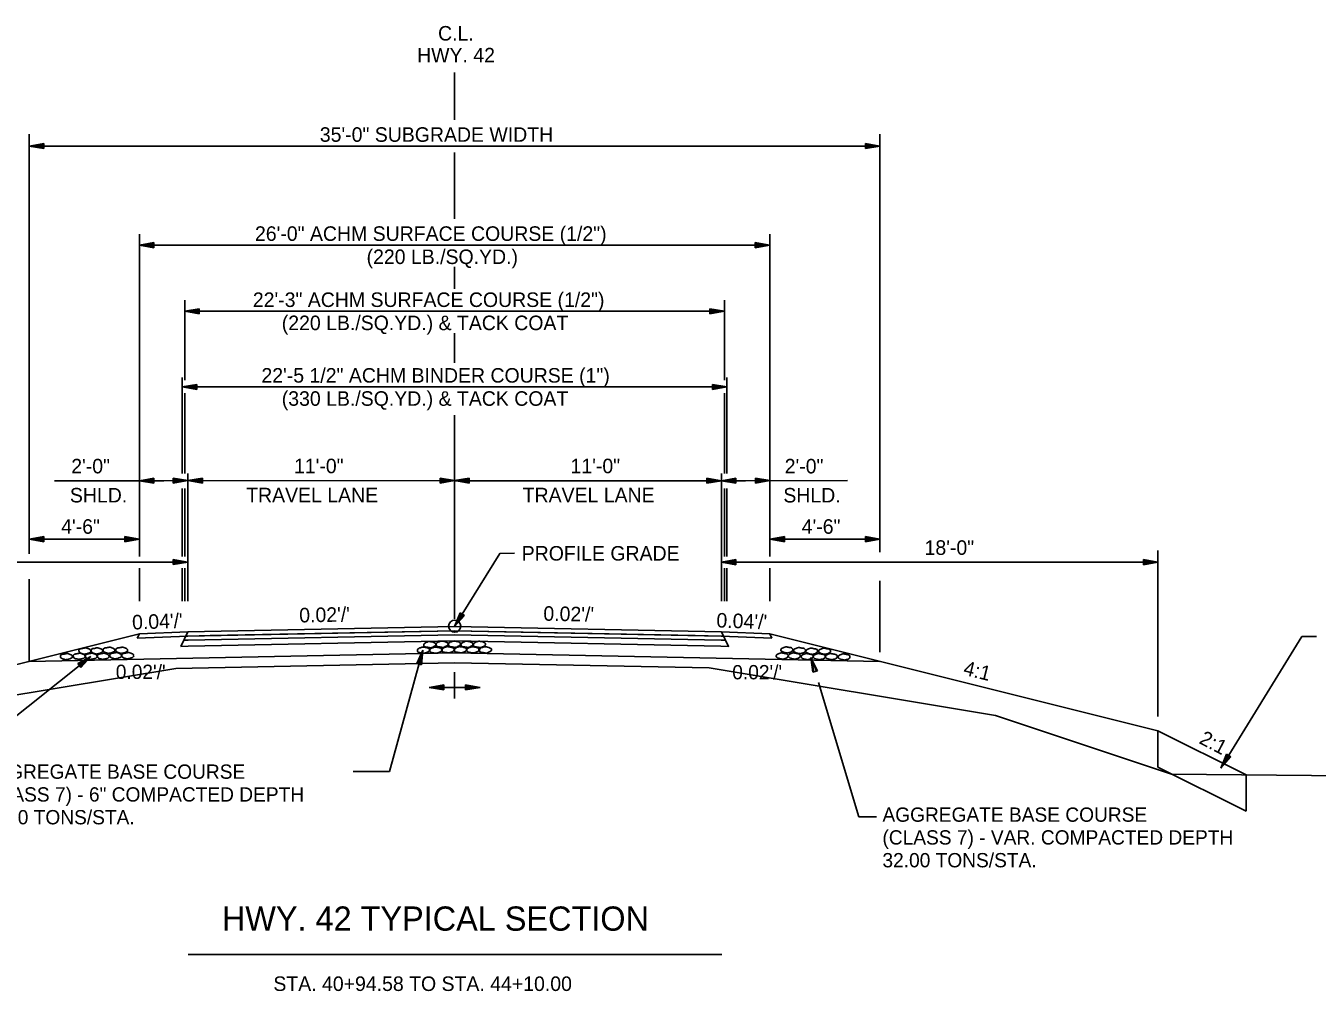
# Model space of a CAD drawing. Extents: x 1461570 to 1461697, y 1686711 to 1686957.
# Drawn here: x 1461599.6 to 1461652.8, y 1686903.7 to 1686943.6 of the extents above; entities that cross this region are included whole.
import ezdxf

# ---------------------------------------------------------------- set-up
doc = ezdxf.new("R2010")
doc.units = 0
for name, color, linetype in [('1', 7, 'Continuous'), ('19', 7, 'Continuous'), ('20', 7, 'Continuous'), ('3', 7, 'Continuous'), ('42', 7, 'Continuous'), ('Default', 7, 'Continuous'), ('Level 1', 7, 'Continuous'), ('Level 9', 7, 'Continuous'), ('R_Draft', 7, 'Continuous'), ('R_Prop Surface', 7, 'Continuous'), ('R_RIP_RAP', 7, 'Continuous')]:
    doc.layers.add(name, color=color, linetype=linetype)

# ---------------------------------------------------------------- blocks, each defined once
blk = doc.blocks.new('ROCKS')
at = {"layer": '1'}
blk.add_spline([(0.013, 0.06), (0.053, 0.053), (0.107, 0.033), (0.133, 0.013), (0.133, -0.007), (0.12, -0.033), (0.107, -0.04), (0.073, -0.053), (0.033, -0.067), (0.013, -0.067), (-0.02, -0.06), (-0.06, -0.053), (-0.087, -0.047), (-0.113, -0.02), (-0.113, -0.007), (-0.107, 0.02), (-0.087, 0.033), (-0.067, 0.047), (-0.033, 0.053), (-0.02, 0.06), (0.013, 0.06)], degree=3, dxfattribs=at)

msp = doc.modelspace()

# ---------------------------------------------------------------- linework, layer by layer
at = {"layer": '19'}
for p, q in [((1461599.708, 1686922.374), (1461600.308, 1686922.479)), ((1461600.308, 1686922.269), (1461599.708, 1686922.374)), ((1461599.868, 1686922.389), (1461600.308, 1686922.424)), ((1461600.308, 1686922.319), (1461599.868, 1686922.359)), ((1461600.308, 1686922.479), (1461600.308, 1686922.269)), ((1461603.646, 1686922.269), (1461603.646, 1686922.479)), ((1461603.646, 1686922.479), (1461604.246, 1686922.374)), ((1461603.646, 1686922.424), (1461604.086, 1686922.389)), ((1461604.246, 1686922.374), (1461603.646, 1686922.269)), ((1461604.086, 1686922.359), (1461603.646, 1686922.319)), ((1461630.245, 1686922.374), (1461630.845, 1686922.479)), ((1461630.845, 1686922.269), (1461630.245, 1686922.374)), ((1461630.405, 1686922.389), (1461630.845, 1686922.424)), ((1461630.845, 1686922.319), (1461630.405, 1686922.359)), ((1461630.845, 1686922.479), (1461630.845, 1686922.269)), ((1461634.183, 1686922.269), (1461634.183, 1686922.479)), ((1461634.183, 1686922.479), (1461634.783, 1686922.374)), ((1461634.183, 1686922.424), (1461634.623, 1686922.389)), ((1461634.783, 1686922.374), (1461634.183, 1686922.269)), ((1461634.623, 1686922.359), (1461634.183, 1686922.319)), ((1461617.246, 1686918.764), (1461617.469, 1686919.33)), ((1461617.647, 1686919.221), (1461617.246, 1686918.764)), ((1461617.319, 1686918.904), (1461617.512, 1686919.298)), ((1461617.606, 1686919.242), (1461617.342, 1686918.893)), ((1461617.469, 1686919.33), (1461617.647, 1686919.221)), ((1461604.246, 1686918.464), (1461604.161, 1686918.293)), ((1461604.246, 1686918.464), (1461604.161, 1686918.293)), ((1461606.246, 1686918.544), (1461604.246, 1686918.464)), ((1461606.246, 1686918.544), (1461605.951, 1686917.948)), ((1461606.161, 1686918.373), (1461606.077, 1686918.203)), ((1461617.246, 1686918.764), (1461606.246, 1686918.544)), ((1461617.246, 1686918.764), (1461606.246, 1686918.544)), ((1461617.246, 1686918.597), (1461606.251, 1686918.377)), ((1461606.251, 1686918.377), (1461607.162, 1686918.395)), ((1461617.246, 1686918.43), (1461606.256, 1686918.21)), ((1461607.162, 1686918.395), (1461617.246, 1686918.597)), ((1461617.246, 1686918.764), (1461628.246, 1686918.544)), ((1461628.246, 1686918.544), (1461617.246, 1686918.764)), ((1461617.246, 1686918.597), (1461628.241, 1686918.377)), ((1461617.246, 1686918.597), (1461617.246, 1686918.597)), ((1461617.246, 1686918.597), (1461617.246, 1686918.597)), ((1461617.246, 1686918.597), (1461627.162, 1686918.399)), ((1461617.246, 1686918.43), (1461628.236, 1686918.21)), ((1461617.246, 1686918.43), (1461617.246, 1686918.43)), ((1461617.246, 1686918.43), (1461617.246, 1686918.43)), ((1461628.241, 1686918.377), (1461630.33, 1686918.293)), ((1461630.246, 1686918.464), (1461628.246, 1686918.544)), ((1461628.54, 1686917.948), (1461628.246, 1686918.544)), ((1461630.246, 1686918.464), (1461628.246, 1686918.544)), ((1461628.246, 1686918.544), (1461628.246, 1686918.544)), ((1461630.33, 1686918.293), (1461630.246, 1686918.464)), ((1461630.33, 1686918.293), (1461630.246, 1686918.464)), ((1461606.077, 1686918.203), (1461605.951, 1686917.948)), ((1461617.246, 1686918.18), (1461606.263, 1686917.96)), ((1461614.564, 1686912.789), (1461615.941, 1686917.799)), ((1461615.941, 1686917.799), (1461615.685, 1686917.247)), ((1461615.887, 1686917.194), (1461615.941, 1686917.799)), ((1461617.246, 1686918.18), (1461628.228, 1686917.96)), ((1461617.246, 1686918.18), (1461617.246, 1686918.18)), ((1461628.54, 1686917.948), (1461628.228, 1686917.96)), ((1461628.414, 1686918.203), (1461628.236, 1686918.21)), ((1461595.484, 1686912.149), (1461602.242, 1686917.535)), ((1461617.246, 1686917.68), (1461599.708, 1686917.329)), ((1461602.242, 1686917.535), (1461601.706, 1686917.247)), ((1461602.11, 1686917.446), (1461601.741, 1686917.207)), ((1461601.806, 1686917.123), (1461602.127, 1686917.424)), ((1461601.836, 1686917.083), (1461602.242, 1686917.535)), ((1461615.888, 1686917.649), (1461615.737, 1686917.236)), ((1461615.839, 1686917.207), (1461615.916, 1686917.641)), ((1461617.246, 1686917.68), (1461634.783, 1686917.329)), ((1461632.013, 1686916.887), (1461631.941, 1686917.49)), ((1461631.941, 1686917.49), (1461632.213, 1686916.945)), ((1461632.06, 1686916.901), (1461631.971, 1686917.333)), ((1461631.998, 1686917.341), (1461632.162, 1686916.933)), ((1461601.706, 1686917.247), (1461601.836, 1686917.083)), ((1461615.685, 1686917.247), (1461615.887, 1686917.194)), ((1461632.213, 1686916.945), (1461632.013, 1686916.887)), ((1461633.912, 1686910.92), (1461632.249, 1686916.465)), ((1461648.847, 1686912.929), (1461649.071, 1686913.496)), ((1461649.248, 1686913.386), (1461648.847, 1686912.929)), ((1461648.921, 1686913.07), (1461649.114, 1686913.464)), ((1461649.208, 1686913.408), (1461648.944, 1686913.059)), ((1461649.071, 1686913.496), (1461649.248, 1686913.386)), ((1461613.066, 1686912.789), (1461614.564, 1686912.789)), ((1461646.812, 1686912.672), (1461660.437, 1686912.552)), ((1461634.649, 1686910.92), (1461633.912, 1686910.92))]:
    msp.add_line(p, q, dxfattribs=at)
for points in [[(1461619.714, 1686921.79), (1461619.114, 1686921.789), (1461617.246, 1686918.764)], [(1461604.161, 1686918.293), (1461606.251, 1686918.377), (1461606.251, 1686918.377)], [(1461606.077, 1686918.203), (1461606.256, 1686918.21), (1461617.246, 1686918.43)], [(1461617.246, 1686918.43), (1461606.256, 1686918.21), (1461606.077, 1686918.203)], [(1461606.251, 1686918.377), (1461606.161, 1686918.373)], [(1461617.246, 1686918.597), (1461606.251, 1686918.377)], [(1461617.246, 1686918.43), (1461628.236, 1686918.21), (1461628.414, 1686918.203), (1461628.33, 1686918.373), (1461628.241, 1686918.377), (1461617.246, 1686918.597)], [(1461617.246, 1686918.597), (1461617.246, 1686918.597)], [(1461617.246, 1686918.43), (1461617.246, 1686918.43)], [(1461617.246, 1686918.43), (1461617.246, 1686918.43)], [(1461617.246, 1686918.43), (1461617.246, 1686918.43), (1461617.246, 1686918.43)], [(1461617.246, 1686918.18), (1461628.228, 1686917.96), (1461628.54, 1686917.948), (1461628.414, 1686918.203), (1461628.236, 1686918.21), (1461617.246, 1686918.43)], [(1461627.162, 1686918.399), (1461628.241, 1686918.377), (1461630.33, 1686918.293)], [(1461652.785, 1686918.357), (1461652.185, 1686918.356), (1461648.847, 1686912.929)], [(1461605.951, 1686917.948), (1461606.263, 1686917.96), (1461617.246, 1686918.18)]]:
    msp.add_lwpolyline(points, dxfattribs=at)
at = {"layer": '20'}
for p, q in [((1461599.708, 1686921.766), (1461599.708, 1686939.085)), ((1461634.783, 1686921.836), (1461634.783, 1686939.085)), ((1461599.708, 1686938.597), (1461600.308, 1686938.702)), ((1461599.708, 1686938.597), (1461634.783, 1686938.597)), ((1461600.308, 1686938.492), (1461599.708, 1686938.597)), ((1461599.868, 1686938.612), (1461600.308, 1686938.647)), ((1461600.308, 1686938.542), (1461599.868, 1686938.582)), ((1461600.308, 1686938.702), (1461600.308, 1686938.492)), ((1461634.183, 1686938.702), (1461634.183, 1686938.492)), ((1461634.783, 1686938.597), (1461634.183, 1686938.702)), ((1461634.623, 1686938.612), (1461634.183, 1686938.647)), ((1461634.183, 1686938.492), (1461634.783, 1686938.597)), ((1461634.183, 1686938.542), (1461634.623, 1686938.582)), ((1461599.708, 1686932.032), (1461599.708, 1686938.169)), ((1461604.246, 1686921.655), (1461604.246, 1686934.959)), ((1461630.246, 1686921.655), (1461630.246, 1686934.959)), ((1461604.246, 1686934.506), (1461604.846, 1686934.611)), ((1461604.246, 1686934.506), (1461630.246, 1686934.506)), ((1461604.846, 1686934.401), (1461604.246, 1686934.506)), ((1461604.406, 1686934.521), (1461604.846, 1686934.556)), ((1461604.846, 1686934.451), (1461604.406, 1686934.491)), ((1461604.846, 1686934.611), (1461604.846, 1686934.401)), ((1461629.646, 1686934.611), (1461629.646, 1686934.401)), ((1461630.246, 1686934.506), (1461629.646, 1686934.611)), ((1461630.086, 1686934.521), (1461629.646, 1686934.556)), ((1461629.646, 1686934.401), (1461630.246, 1686934.506)), ((1461629.646, 1686934.451), (1461630.086, 1686934.491)), ((1461606.119, 1686928.94), (1461606.119, 1686932.231)), ((1461628.372, 1686928.94), (1461628.372, 1686932.232)), ((1461606.119, 1686931.778), (1461606.719, 1686931.883)), ((1461606.119, 1686931.778), (1461628.372, 1686931.778)), ((1461606.719, 1686931.673), (1461606.119, 1686931.778)), ((1461606.279, 1686931.793), (1461606.719, 1686931.828)), ((1461606.719, 1686931.723), (1461606.279, 1686931.763)), ((1461606.719, 1686931.883), (1461606.719, 1686931.673)), ((1461627.772, 1686931.883), (1461627.772, 1686931.673)), ((1461628.372, 1686931.778), (1461627.772, 1686931.883)), ((1461628.212, 1686931.793), (1461627.772, 1686931.828)), ((1461627.772, 1686931.673), (1461628.372, 1686931.778)), ((1461627.772, 1686931.723), (1461628.212, 1686931.763)), ((1461606.014, 1686925.087), (1461606.014, 1686929.041)), ((1461628.477, 1686925.087), (1461628.477, 1686929.041)), ((1461606.014, 1686928.656), (1461606.614, 1686928.761)), ((1461606.014, 1686928.656), (1461628.477, 1686928.656)), ((1461606.614, 1686928.551), (1461606.014, 1686928.656)), ((1461606.174, 1686928.671), (1461606.614, 1686928.706)), ((1461606.614, 1686928.601), (1461606.174, 1686928.641)), ((1461606.614, 1686928.761), (1461606.614, 1686928.551)), ((1461627.877, 1686928.761), (1461627.877, 1686928.551)), ((1461628.477, 1686928.656), (1461627.877, 1686928.761)), ((1461628.317, 1686928.671), (1461627.877, 1686928.706)), ((1461627.877, 1686928.551), (1461628.477, 1686928.656)), ((1461627.877, 1686928.601), (1461628.317, 1686928.641)), ((1461606.119, 1686925.087), (1461606.119, 1686928.395)), ((1461628.372, 1686925.087), (1461628.372, 1686928.395)), ((1461604.246, 1686924.788), (1461604.846, 1686924.894)), ((1461604.846, 1686924.684), (1461604.246, 1686924.788)), ((1461604.406, 1686924.804), (1461604.846, 1686924.839)), ((1461604.846, 1686924.734), (1461604.406, 1686924.774)), ((1461604.846, 1686924.894), (1461604.846, 1686924.684)), ((1461605.646, 1686924.894), (1461605.646, 1686924.684)), ((1461606.246, 1686924.789), (1461605.646, 1686924.894)), ((1461606.086, 1686924.804), (1461605.646, 1686924.839)), ((1461605.646, 1686924.684), (1461606.246, 1686924.789)), ((1461605.646, 1686924.734), (1461606.086, 1686924.774)), ((1461606.246, 1686919.819), (1461606.246, 1686925.087)), ((1461606.246, 1686924.789), (1461606.846, 1686924.894)), ((1461606.846, 1686924.684), (1461606.246, 1686924.789)), ((1461606.406, 1686924.804), (1461606.846, 1686924.839)), ((1461606.846, 1686924.734), (1461606.406, 1686924.774)), ((1461606.846, 1686924.894), (1461606.846, 1686924.684)), ((1461616.646, 1686924.894), (1461616.646, 1686924.684)), ((1461617.246, 1686924.789), (1461616.646, 1686924.894)), ((1461617.086, 1686924.804), (1461616.646, 1686924.839)), ((1461616.646, 1686924.684), (1461617.246, 1686924.789)), ((1461616.646, 1686924.734), (1461617.086, 1686924.774)), ((1461617.246, 1686924.789), (1461617.846, 1686924.894)), ((1461617.846, 1686924.684), (1461617.246, 1686924.789)), ((1461617.406, 1686924.804), (1461617.846, 1686924.839)), ((1461617.846, 1686924.734), (1461617.406, 1686924.774)), ((1461617.846, 1686924.894), (1461617.846, 1686924.684)), ((1461627.646, 1686924.893), (1461627.646, 1686924.683)), ((1461628.246, 1686924.788), (1461627.646, 1686924.893)), ((1461628.086, 1686924.803), (1461627.646, 1686924.838)), ((1461627.646, 1686924.683), (1461628.246, 1686924.788)), ((1461627.646, 1686924.733), (1461628.086, 1686924.773)), ((1461628.246, 1686919.818), (1461628.246, 1686925.087)), ((1461628.246, 1686924.788), (1461628.846, 1686924.893)), ((1461628.846, 1686924.683), (1461628.246, 1686924.788)), ((1461628.406, 1686924.803), (1461628.846, 1686924.838)), ((1461628.846, 1686924.733), (1461628.406, 1686924.773)), ((1461628.846, 1686924.893), (1461628.846, 1686924.683)), ((1461629.651, 1686924.894), (1461629.651, 1686924.684)), ((1461630.251, 1686924.789), (1461629.651, 1686924.894)), ((1461630.091, 1686924.804), (1461629.651, 1686924.839)), ((1461629.651, 1686924.684), (1461630.251, 1686924.789)), ((1461629.651, 1686924.734), (1461630.091, 1686924.774)), ((1461606.014, 1686921.655), (1461606.014, 1686924.467)), ((1461606.119, 1686921.655), (1461606.119, 1686924.467)), ((1461628.372, 1686921.655), (1461628.372, 1686924.467)), ((1461628.477, 1686921.655), (1461628.477, 1686924.467)), ((1461605.646, 1686921.533), (1461605.646, 1686921.323)), ((1461606.246, 1686921.428), (1461605.646, 1686921.533)), ((1461628.246, 1686921.427), (1461628.846, 1686921.532)), ((1461628.846, 1686921.532), (1461628.846, 1686921.322)), ((1461645.646, 1686921.532), (1461645.646, 1686921.322)), ((1461646.246, 1686921.427), (1461645.646, 1686921.532)), ((1461646.246, 1686915.058), (1461646.246, 1686921.9)), ((1461604.246, 1686919.819), (1461604.246, 1686921.171)), ((1461606.086, 1686921.443), (1461605.646, 1686921.478)), ((1461605.646, 1686921.323), (1461606.246, 1686921.428)), ((1461605.646, 1686921.373), (1461606.086, 1686921.413)), ((1461606.014, 1686919.819), (1461606.014, 1686921.171)), ((1461606.119, 1686919.819), (1461606.119, 1686921.171)), ((1461628.846, 1686921.322), (1461628.246, 1686921.427)), ((1461628.372, 1686919.818), (1461628.372, 1686921.171)), ((1461628.406, 1686921.442), (1461628.846, 1686921.477)), ((1461628.846, 1686921.372), (1461628.406, 1686921.412)), ((1461628.477, 1686919.818), (1461628.477, 1686921.171)), ((1461630.246, 1686919.818), (1461630.246, 1686921.171)), ((1461646.086, 1686921.442), (1461645.646, 1686921.477)), ((1461645.646, 1686921.322), (1461646.246, 1686921.427)), ((1461645.646, 1686921.372), (1461646.086, 1686921.412)), ((1461599.708, 1686917.329), (1461599.708, 1686920.717)), ((1461634.783, 1686917.713), (1461634.783, 1686920.65))]:
    msp.add_line(p, q, dxfattribs=at)
at = {"layer": '3'}
msp.add_line((1461606.26, 1686905.229), (1461628.26, 1686905.229), dxfattribs=at)
at = {"layer": '42'}
for p, q in [((1461617.246, 1686939.673), (1461617.246, 1686941.629)), ((1461617.246, 1686935.596), (1461617.246, 1686938.334)), ((1461617.246, 1686932.701), (1461617.246, 1686933.609)), ((1461617.246, 1686929.657), (1461617.246, 1686930.874)), ((1461617.246, 1686919.084), (1461617.246, 1686927.494)), ((1461600.741, 1686924.788), (1461605.251, 1686924.788)), ((1461605.246, 1686924.788), (1461617.246, 1686924.789)), ((1461629.246, 1686924.788), (1461617.246, 1686924.788)), ((1461633.453, 1686924.789), (1461628.24, 1686924.788)), ((1461588.246, 1686921.428), (1461606.246, 1686921.428)), ((1461646.246, 1686921.427), (1461628.246, 1686921.427)), ((1461617.246, 1686916.891), (1461617.246, 1686915.804)), ((1461616.798, 1686916.361), (1461616.198, 1686916.256)), ((1461616.198, 1686916.256), (1461616.798, 1686916.151)), ((1461616.198, 1686916.256), (1461618.293, 1686916.256)), ((1461616.798, 1686916.306), (1461616.358, 1686916.271)), ((1461616.358, 1686916.241), (1461616.798, 1686916.201)), ((1461616.798, 1686916.151), (1461616.798, 1686916.361)), ((1461617.693, 1686916.151), (1461617.693, 1686916.361)), ((1461617.693, 1686916.361), (1461618.293, 1686916.256)), ((1461617.693, 1686916.306), (1461618.133, 1686916.271)), ((1461618.293, 1686916.256), (1461617.693, 1686916.151)), ((1461618.133, 1686916.241), (1461617.693, 1686916.201))]:
    msp.add_line(p, q, dxfattribs=at)
msp.add_circle((1461617.25, 1686918.782), 0.25, dxfattribs=at)
at = {"layer": 'Level 9'}
for p, q in [((1461604.246, 1686922.374), (1461599.708, 1686922.374)), ((1461634.783, 1686922.374), (1461630.245, 1686922.374))]:
    msp.add_line(p, q, dxfattribs=at)
at = {"layer": 'R_Draft'}
for p, q in [((1461617.246, 1686917.271), (1461605.746, 1686917.041)), ((1461617.246, 1686917.271), (1461627.746, 1686917.061)), ((1461596.367, 1686915.478), (1461605.746, 1686917.041)), ((1461639.547, 1686915.094), (1461627.746, 1686917.061)), ((1461646.812, 1686912.672), (1461639.547, 1686915.094))]:
    msp.add_line(p, q, dxfattribs=at)
at = {"layer": 'R_Prop Surface'}
for p, q in [((1461604.246, 1686918.464), (1461588.246, 1686914.464)), ((1461606.251, 1686918.377), (1461604.161, 1686918.293)), ((1461606.246, 1686918.544), (1461604.246, 1686918.464)), ((1461630.246, 1686918.464), (1461646.246, 1686914.464)), ((1461606.263, 1686917.96), (1461605.951, 1686917.948)), ((1461606.256, 1686918.21), (1461606.077, 1686918.203)), ((1461646.246, 1686914.464), (1461649.883, 1686912.645))]:
    msp.add_line(p, q, dxfattribs=at)
at = {"layer": 'R_RIP_RAP'}
for p, q in [((1461649.883, 1686912.645), (1461646.246, 1686914.464)), ((1461646.246, 1686914.464), (1461646.246, 1686912.964)), ((1461646.246, 1686912.964), (1461646.246, 1686912.964)), ((1461649.883, 1686911.583), (1461649.883, 1686912.645)), ((1461649.883, 1686911.145), (1461649.883, 1686911.583)), ((1461649.883, 1686911.583), (1461649.883, 1686911.583)), ((1461649.883, 1686911.583), (1461649.883, 1686911.583))]:
    msp.add_line(p, q, dxfattribs=at)
msp.add_lwpolyline([(1461646.246, 1686912.964), (1461649.883, 1686911.145)], dxfattribs=at)

# ---------------------------------------------------------------- block references
at = {"layer": '1', "xscale": 1.968733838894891, "yscale": -1.968733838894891}
for p in [(1461601.98, 1686917.752), (1461602.476, 1686917.758), (1461602.974, 1686917.784), (1461603.499, 1686917.784), (1461601.219, 1686917.522), (1461601.744, 1686917.535), (1461602.242, 1686917.535), (1461602.738, 1686917.535), (1461603.25, 1686917.561), (1461603.749, 1686917.561)]:
    msp.add_blockref('ROCKS', p, dxfattribs=at)
at = {"layer": '1', "xscale": 1.968733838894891, "yscale": 1.968733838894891, "rotation": 180}
for p in [(1461630.965, 1686917.797), (1461631.49, 1686917.77), (1461631.989, 1686917.744), (1461632.52, 1686917.745), (1461630.773, 1686917.547), (1461631.272, 1686917.547), (1461631.802, 1686917.52), (1461632.301, 1686917.52), (1461632.8, 1686917.52), (1461633.325, 1686917.507)]:
    msp.add_blockref('ROCKS', p, dxfattribs=at)
at = {"layer": 'Level 1', "xscale": 2.011654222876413, "yscale": 2.011654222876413, "rotation": 1.8263814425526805}
for p in [(1461615.941, 1686917.799), (1461616.201, 1686918.026), (1461616.446, 1686917.798), (1461616.71, 1686918.043), (1461616.955, 1686917.814), (1461617.221, 1686918.044), (1461617.465, 1686917.815), (1461617.736, 1686918.04), (1461617.981, 1686917.812), (1461618.252, 1686918.037), (1461618.496, 1686917.808)]:
    msp.add_blockref('ROCKS', p, dxfattribs=at)

# ---------------------------------------------------------------- texts
at = {"layer": '19'}
for s, height, rotation, p in [('2\'-0"', 0.6, 360, (1461601.438, 1686925.089)), ('11\'-0"', 0.6, 360, (1461610.623, 1686925.095)), ('SHLD.', 0.6, 360, (1461601.383, 1686923.889)), ('TRAVEL LANE', 0.6, 360, (1461608.651, 1686923.895)), ('PROFILE GRADE', 0.6, 360, (1461620.014, 1686921.49)), ("0.02'/'", 0.6, 1.1458, (1461610.845, 1686918.936)), ("0.02'/'", 0.6, 358.8542, (1461620.901, 1686919.011)), ("0.04'/'", 0.6, 2.1602, (1461603.957, 1686918.642)), ("0.04'/'", 0.6, 357.8398, (1461628.033, 1686918.735)), ('4:1', 0.6, 345.9638, (1461638.188, 1686916.788)), ('2:1', 0.6, 332.3642, (1461647.906, 1686913.97)), ('AGGREGATE BASE COURSE', 0.59001, 360, (1461597.696, 1686912.486)), ('(CLASS 7) - 6" COMPACTED DEPTH', 0.59001, 360, (1461597.696, 1686911.546)), ('85.50 TONS/STA.', 0.59001, 360, (1461597.696, 1686910.606)), ('AGGREGATE BASE COURSE', 0.59001, 360, (1461634.888, 1686910.712)), ('(CLASS 7) - VAR. COMPACTED DEPTH', 0.59001, 360, (1461634.888, 1686909.772)), ('32.00 TONS/STA.', 0.59001, 360, (1461634.888, 1686908.832)), ('HWY. 42 TYPICAL SECTION', 1, 359.9954, (1461607.649, 1686906.218)), ('STA. 40+94.58 TO STA. 44+10.00', 0.6, 359.9954, (1461609.773, 1686903.73))]:
    msp.add_text(s, height=height, rotation=rotation, dxfattribs=at).set_placement(p)
for s, height, p in [('11\'-0"', 0.6, (1461622.026, 1686925.095)), ('2\'-0"', 0.6, (1461630.857, 1686925.088)), ('TRAVEL LANE', 0.6, (1461620.053, 1686923.895)), ('SHLD.', 0.6, (1461630.802, 1686923.888)), ('4\'-6"', 0.6, (1461601.022, 1686922.597)), ('4\'-6"', 0.6, (1461631.559, 1686922.597)), ('18\'-0"', 0.6, (1461636.625, 1686921.727)), ("0.02'/'", 0.59, (1461603.274, 1686916.605)), ("0.02'/'", 0.59, (1461628.695, 1686916.59))]:
    msp.add_text(s, height=height, dxfattribs=at).set_placement(p)
at = {"layer": 'Default'}
for s, p in [('35\'-0" SUBGRADE WIDTH', (1461611.688, 1686938.772)), ('26\'-0" ACHM SURFACE COURSE (1/2")', (1461609.014, 1686934.684)), ('(220 LB./SQ.YD.)', (1461613.616, 1686933.728)), ('22\'-3" ACHM SURFACE COURSE (1/2")', (1461608.926, 1686931.956)), ('(220 LB./SQ.YD.) & TACK COAT', (1461610.119, 1686931)), ('22\'-5 1/2" ACHM BINDER COURSE (1")', (1461609.28, 1686928.834)), ('(330 LB./SQ.YD.) & TACK COAT', (1461610.119, 1686927.878))]:
    msp.add_text(s, height=0.60001, dxfattribs=at).set_placement(p)
at = {"layer": 'R_Draft'}
for s, p in [('C.L.', (1461616.564, 1686942.95)), ('HWY. 42', (1461615.7, 1686942.05))]:
    msp.add_text(s, height=0.6, rotation=360, dxfattribs=at).set_placement(p)

doc.saveas('drawing.dxf')
